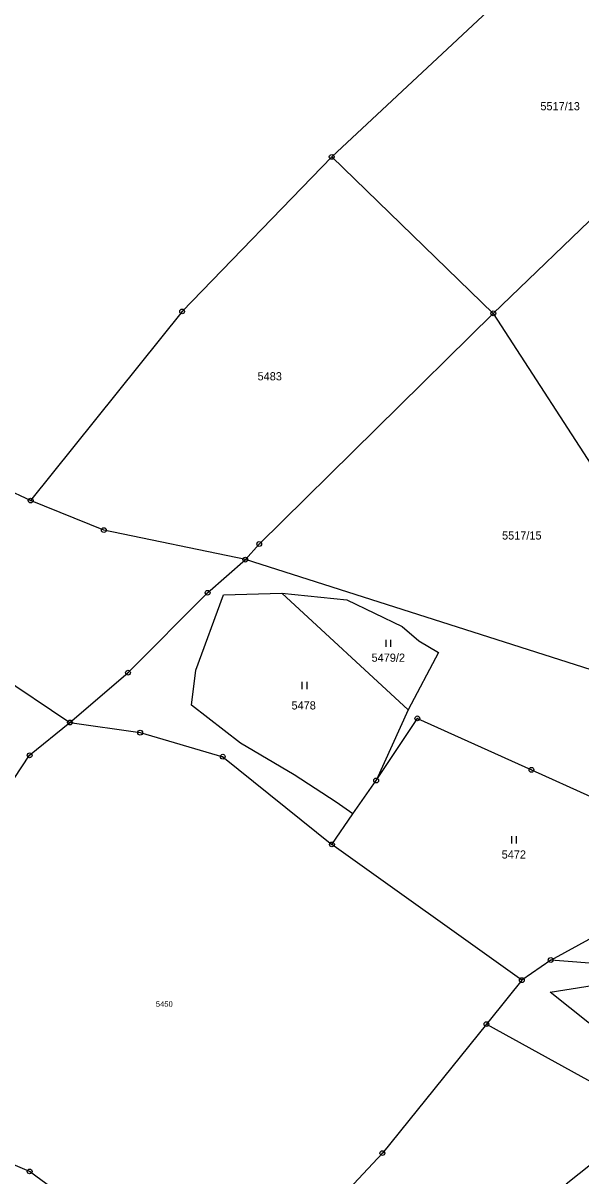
# Model space of a CAD drawing. Extents: x -644096 to -634268, y -1141430 to -1133463.
# Drawn here: x -638438.7 to -638322.7, y -1140185.1 to -1139945.5 of the extents above; entities that cross this region are included whole.
import ezdxf

# ---------------------------------------------------------------- set-up
doc = ezdxf.new("R2010")
doc.units = 0
for name, color, linetype in [('_CIVIL_CONSTRUCTION', 7, 'Continuous'), ('svrsek_osa_sjezdy', 7, 'Continuous'), ('svrsek_osa_VRT', 7, 'Continuous'), ('terminal_VRT', 7, 'Continuous')]:
    doc.layers.add(name, color=color, linetype=linetype)

msp = doc.modelspace()

# ---------------------------------------------------------------- linework, layer by layer
at = {"layer": '_CIVIL_CONSTRUCTION'}
for centre, radius in [((-638374.5, -1139973.29), 0.5), ((-638374.5, -1139973.29), 0.0303), ((-638405.61, -1140005.41), 0.5), ((-638405.61, -1140005.41), 0.0303), ((-638340.91, -1140005.81), 0.5), ((-638340.91, -1140005.81), 0.0303), ((-638437.1, -1140044.73), 0.5), ((-638437.1, -1140044.73), 0.0303), ((-638421.89, -1140050.86), 0.5), ((-638421.89, -1140050.86), 0.0303), ((-638389.57, -1140053.76), 0.5), ((-638389.57, -1140053.76), 0.0303), ((-638392.46, -1140057), 0.5), ((-638392.46, -1140057), 0.0303), ((-638400.31, -1140063.89), 0.5), ((-638400.31, -1140063.89), 0.0303), ((-638416.87, -1140080.51), 0.5), ((-638416.87, -1140080.51), 0.0303), ((-638428.93, -1140090.86), 0.5), ((-638356.69, -1140090), 0.5), ((-638356.69, -1140090), 0.0303), ((-638428.93, -1140090.86), 0.0303), ((-638414.32, -1140092.97), 0.5), ((-638414.32, -1140092.97), 0.0303), ((-638437.31, -1140097.67), 0.5), ((-638437.31, -1140097.67), 0.0303), ((-638397.16, -1140097.97), 0.5), ((-638397.16, -1140097.97), 0.0303), ((-638365.26, -1140102.91), 0.5), ((-638332.98, -1140100.7), 0.5), ((-638332.98, -1140100.7), 0.0303), ((-638365.26, -1140102.91), 0.0303), ((-638374.46, -1140116.2), 0.5), ((-638374.46, -1140116.2), 0.0303), ((-638328.98, -1140140.23), 0.5), ((-638328.98, -1140140.23), 0.0303), ((-638334.97, -1140144.41), 0.5), ((-638334.97, -1140144.41), 0.0303), ((-638342.34, -1140153.55), 0.5), ((-638342.34, -1140153.55), 0.0303), ((-638363.97, -1140180.36), 0.5), ((-638363.97, -1140180.36), 0.0303), ((-638437.31, -1140184.17), 0.5), ((-638437.31, -1140184.17), 0.0303)]:
    msp.add_circle(centre, radius, dxfattribs=at)
at = {"layer": 'svrsek_osa_sjezdy'}
for p, q in [((-638363.21, -1140075.15), (-638363.21, -1140073.65)), ((-638362.21, -1140075.15), (-638362.21, -1140073.65)), ((-638380.63, -1140083.91), (-638380.63, -1140082.41)), ((-638379.63, -1140083.91), (-638379.63, -1140082.41)), ((-638337.06, -1140116.01), (-638337.06, -1140114.51)), ((-638336.06, -1140116.01), (-638336.06, -1140114.51))]:
    msp.add_line(p, q, dxfattribs=at)
at = {"layer": 'terminal_VRT'}
for p, q in [((-638340.91, -1140005.81), (-638374.5, -1139973.29)), ((-638316.21, -1139982.04), (-638340.91, -1140005.81)), ((-638340.91, -1140005.81), (-638294.42, -1140077.71)), ((-638305.77, -1140084.62), (-638392.46, -1140057)), ((-638358.61, -1140088.22), (-638384.88, -1140063.98)), ((-638464.4, -1140067.02), (-638428.93, -1140090.86)), ((-638358.61, -1140088.22), (-638365.26, -1140102.91)), ((-638370.08, -1140109.86), (-638365.26, -1140102.91)), ((-638374.46, -1140116.2), (-638370.08, -1140109.86)), ((-638334.97, -1140144.41), (-638374.46, -1140116.2)), ((-638328.98, -1140140.23), (-638291.07, -1140119.58)), ((-638328.98, -1140140.23), (-638334.97, -1140144.41)), ((-638279.83, -1140144.22), (-638328.98, -1140140.23)), ((-638334.97, -1140144.41), (-638337.82, -1140147.94)), ((-638337.82, -1140147.94), (-638342.34, -1140153.55)), ((-638342.34, -1140153.55), (-638308.02, -1140172.53)), ((-638325.73, -1140186.75), (-638308.02, -1140172.53))]:
    msp.add_line(p, q, dxfattribs=at)
for points in [[(-638374.5, -1139973.29), (-638334.75, -1139936.15), (-638316.38, -1139922.17)], [(-638374.5, -1139973.29), (-638405.61, -1140005.41), (-638437.1, -1140044.73)], [(-638392.46, -1140057), (-638389.57, -1140053.76), (-638340.91, -1140005.81)], [(-638437.1, -1140044.73), (-638469.21, -1140029.78), (-638490.54, -1140015.77)], [(-638392.46, -1140057), (-638421.89, -1140050.86), (-638437.1, -1140044.73)], [(-638428.93, -1140090.86), (-638416.87, -1140080.51), (-638400.31, -1140063.89), (-638392.46, -1140057)], [(-638370.08, -1140109.86), (-638373.57, -1140107.39), (-638382.28, -1140101.77), (-638393.48, -1140095.14), (-638403.67, -1140087.24), (-638402.79, -1140079.96), (-638396.98, -1140064.3), (-638384.88, -1140063.98)], [(-638384.88, -1140063.98), (-638371.35, -1140065.33), (-638359.89, -1140070.91), (-638356.4, -1140073.87), (-638352.3, -1140076.31), (-638358.61, -1140088.22)], [(-638365.26, -1140102.91), (-638356.69, -1140090), (-638332.98, -1140100.7), (-638320.67, -1140106.24), (-638303.55, -1140114.35), (-638291.07, -1140119.58)], [(-638462.55, -1140133.71), (-638456.14, -1140126.15), (-638437.31, -1140097.67), (-638428.93, -1140090.86)], [(-638428.93, -1140090.86), (-638414.32, -1140092.97), (-638397.16, -1140097.97), (-638374.46, -1140116.2)], [(-638312.92, -1140144.34), (-638289.9, -1140150.52), (-638300.97, -1140160.2), (-638317.19, -1140156.43), (-638329.07, -1140146.93), (-638312.92, -1140144.34)], [(-638342.34, -1140153.55), (-638363.97, -1140180.36), (-638395.93, -1140214.58)], [(-638395.93, -1140214.58), (-638437.31, -1140184.17), (-638454.51, -1140176.87), (-638488.44, -1140164.28)]]:
    msp.add_lwpolyline(points, dxfattribs=at)

# ---------------------------------------------------------------- texts
at = {"layer": 'svrsek_osa_VRT'}
for s, height, p in [('5517/13', 1.7, (-638331.12, -1139963.6)), ('5483', 1.7, (-638389.92, -1140019.74)), ('5517/15', 1.7, (-638339.09, -1140052.83)), ('5479/2', 1.7, (-638366.22, -1140078.23)), ('5478', 1.7, (-638382.87, -1140088.15)), ('5472', 1.7, (-638339.17, -1140119.14)), ('5450', 1.14, (-638411.06, -1140149.94))]:
    msp.add_text(s, height=height, dxfattribs=at).set_placement(p)

doc.saveas('drawing.dxf')
